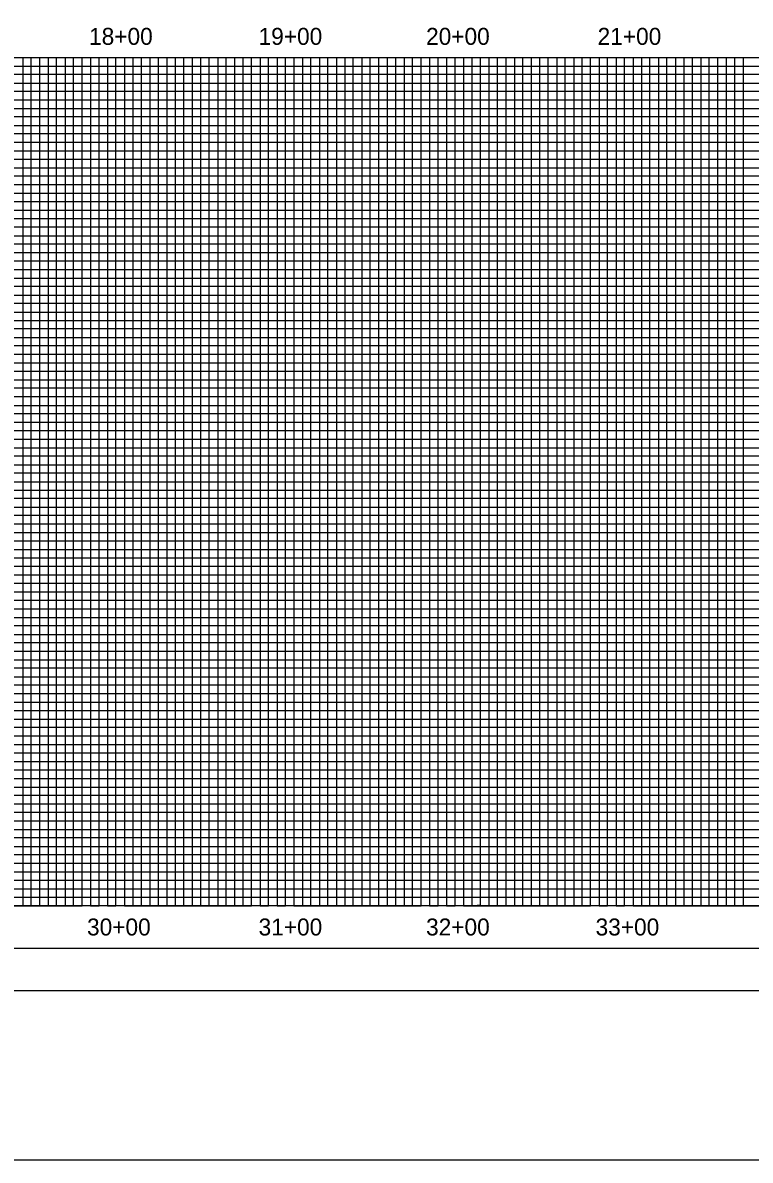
# Model space of a CAD drawing. Extents: x 505569 to 516904, y 436011 to 484484.
# Drawn here: x 506359 to 506788, y 483009 to 483679 of the extents above; entities that cross this region are included whole.
import ezdxf

# ---------------------------------------------------------------- set-up
doc = ezdxf.new("R2010")
doc.units = 0
for name, color, linetype in [('COGO Default Curve', 7, 'Continuous'), ('Exist Profile Cell', 7, 'Continuous'), ('Prop Grid Mask', 7, 'Continuous'), ('Prop Vertical Profile Curve Label', 7, 'Continuous'), ('Prop Vertical Profile Grade', 7, 'Continuous'), ('Prop Vertical Profile Grade Label', 7, 'Continuous'), ('Scratch_Level_2', 7, 'Continuous')]:
    doc.layers.add(name, color=color, linetype=linetype)

msp = doc.modelspace()

# ---------------------------------------------------------------- linework, layer by layer
at = {"layer": 'COGO Default Curve'}
for points in [[(506344.08, 483158.71), (506394.08, 483158.71), (506394.08, 483158.71), (506394.08, 483658.71), (506444.08, 483658.71), (506444.08, 483158.71), (506494.08, 483158.71), (506494.08, 483658.71), (506544.08, 483658.71), (506544.08, 483158.71), (506594.08, 483158.71), (506594.08, 483658.71), (506644.08, 483658.71), (506644.08, 483158.71), (506694.08, 483158.71), (506694.08, 483658.71), (506744.08, 483658.71), (506744.08, 483158.71), (506794.08, 483158.71)], [(505769.08, 483633.71), (507269.08, 483633.71)], [(507269.08, 483583.71), (505769.08, 483583.71), (505769.08, 483533.71), (507269.08, 483533.71)], [(507269.08, 483483.71), (505769.08, 483483.71), (505769.08, 483433.71), (507269.08, 483433.71)], [(507269.08, 483383.71), (505769.08, 483383.71), (505769.08, 483333.71), (507269.08, 483333.71)], [(507269.08, 483283.71), (505769.08, 483283.71), (505769.08, 483233.71), (507269.08, 483233.71)], [(507269.08, 483183.71), (505769.08, 483183.71)]]:
    msp.add_lwpolyline(points, dxfattribs=at)
at = {"layer": 'Prop Grid Mask'}
msp.add_lwpolyline([(505602.08, 483108.71), (507286.08, 483108.71), (507286.08, 484208.71), (505602.08, 484208.71)], close=True, dxfattribs=at)
at = {"layer": 'Prop Vertical Profile Curve Label'}
for p, q in [((505769.08, 483658.71), (507269.08, 483658.71)), ((507269.08, 483158.71), (505769.08, 483158.71)), ((505769.08, 483133.71), (507269.08, 483133.71))]:
    msp.add_line(p, q, dxfattribs=at)
msp.add_lwpolyline([(507269.08, 484183.71), (505769.08, 484183.71), (505769.08, 483133.71), (507269.08, 483133.71)], close=True, dxfattribs=at)
at = {"layer": 'Prop Vertical Profile Grade'}
for points in [[(505819.08, 483658.71), (507219.08, 483658.71), (507219.08, 483158.71), (505819.08, 483158.71)], [(505569.08, 483508.71), (506969.08, 483508.71), (506969.08, 483008.71), (505569.08, 483008.71)]]:
    msp.add_lwpolyline(points, close=True, dxfattribs=at)
at = {"layer": 'Prop Vertical Profile Grade Label'}
for p, q in [((505819.08, 483653.71), (507219.08, 483653.71)), ((507219.08, 483648.71), (505819.08, 483648.71)), ((505819.08, 483643.71), (507219.08, 483643.71)), ((507219.08, 483638.71), (505819.08, 483638.71)), ((505819.08, 483628.71), (507219.08, 483628.71)), ((507219.08, 483623.71), (505819.08, 483623.71)), ((505819.08, 483618.71), (507219.08, 483618.71)), ((507219.08, 483613.71), (505819.08, 483613.71)), ((505819.08, 483603.71), (507219.08, 483603.71)), ((507219.08, 483598.71), (505819.08, 483598.71)), ((505819.08, 483593.71), (507219.08, 483593.71)), ((507219.08, 483588.71), (505819.08, 483588.71)), ((505819.08, 483578.71), (507219.08, 483578.71)), ((507219.08, 483573.71), (505819.08, 483573.71)), ((505819.08, 483568.71), (507219.08, 483568.71)), ((507219.08, 483563.71), (505819.08, 483563.71)), ((505819.08, 483553.71), (507219.08, 483553.71)), ((507219.08, 483548.71), (505819.08, 483548.71)), ((505819.08, 483543.71), (507219.08, 483543.71)), ((507219.08, 483538.71), (505819.08, 483538.71)), ((505819.08, 483528.71), (507219.08, 483528.71)), ((507219.08, 483523.71), (505819.08, 483523.71)), ((505819.08, 483518.71), (507219.08, 483518.71)), ((507219.08, 483513.71), (505819.08, 483513.71)), ((505819.08, 483503.71), (507219.08, 483503.71)), ((507219.08, 483498.71), (505819.08, 483498.71)), ((505819.08, 483493.71), (507219.08, 483493.71)), ((507219.08, 483488.71), (505819.08, 483488.71)), ((505819.08, 483478.71), (507219.08, 483478.71)), ((507219.08, 483473.71), (505819.08, 483473.71)), ((505819.08, 483468.71), (507219.08, 483468.71)), ((507219.08, 483463.71), (505819.08, 483463.86)), ((505819.08, 483453.71), (507219.08, 483453.71)), ((507219.08, 483448.71), (505819.08, 483448.71)), ((505819.08, 483443.71), (507219.08, 483443.71)), ((507219.08, 483438.71), (505819.08, 483438.71)), ((505819.08, 483428.71), (507219.08, 483428.71)), ((507219.08, 483423.71), (505819.08, 483423.71)), ((505819.08, 483418.71), (507219.08, 483418.71)), ((507219.08, 483413.71), (505819.08, 483413.71)), ((505819.08, 483403.71), (507219.08, 483403.71)), ((507219.08, 483398.71), (505819.08, 483398.71)), ((505819.08, 483393.71), (507219.08, 483393.71)), ((507219.08, 483388.71), (505819.08, 483388.71)), ((505819.08, 483378.71), (507219.08, 483378.71)), ((507219.08, 483373.71), (505819.08, 483373.71)), ((505819.08, 483368.71), (507219.08, 483368.71)), ((507219.08, 483363.71), (505819.08, 483363.71)), ((505819.08, 483353.71), (507219.08, 483353.71)), ((507219.08, 483348.71), (505819.08, 483348.71)), ((505819.08, 483343.71), (507219.08, 483343.71)), ((507219.08, 483338.71), (505819.08, 483338.71)), ((505819.08, 483328.71), (507219.08, 483328.71)), ((507219.08, 483323.71), (505819.08, 483323.71)), ((505819.08, 483318.71), (507219.08, 483318.71)), ((507219.08, 483313.71), (505819.08, 483313.71)), ((505819.08, 483303.71), (507219.08, 483303.71)), ((507219.08, 483298.71), (505819.08, 483298.71)), ((505819.08, 483293.71), (507219.08, 483293.71)), ((507219.08, 483288.71), (505819.08, 483288.71)), ((505819.08, 483278.71), (507219.08, 483278.71)), ((507219.08, 483273.71), (505819.08, 483273.71)), ((505819.08, 483268.71), (507219.08, 483268.71)), ((507219.08, 483263.71), (505819.08, 483263.71)), ((505819.08, 483253.71), (507219.08, 483253.71)), ((507219.08, 483248.71), (505819.08, 483248.71)), ((505819.08, 483243.71), (507219.08, 483243.71)), ((507219.08, 483238.71), (505819.08, 483238.71)), ((505819.08, 483228.71), (507219.08, 483228.71)), ((507219.08, 483223.71), (505819.08, 483223.71)), ((505819.08, 483218.71), (507219.08, 483218.71)), ((507219.08, 483213.71), (505819.08, 483213.71)), ((505819.08, 483203.71), (507219.08, 483203.71)), ((507219.08, 483198.71), (505819.08, 483198.71)), ((505819.08, 483193.71), (507219.08, 483193.71)), ((507219.08, 483188.71), (505819.08, 483188.71)), ((505819.08, 483178.71), (507219.08, 483178.71)), ((507219.08, 483173.71), (505819.08, 483173.71)), ((505819.08, 483168.71), (507219.08, 483168.71)), ((505819.08, 483163.71), (507219.08, 483163.71))]:
    msp.add_line(p, q, dxfattribs=at)
for points in [[(506354.08, 483658.71), (506359.08, 483658.71), (506359.08, 483158.71), (506364.08, 483158.71), (506364.08, 483658.71), (506374.08, 483658.71), (506374.08, 483158.71), (506379.08, 483158.71), (506379.08, 483658.71), (506384.08, 483658.71), (506384.08, 483158.71), (506389.08, 483158.71), (506389.08, 483658.71), (506399.08, 483658.71), (506399.08, 483158.71), (506404.08, 483158.71), (506404.08, 483658.71), (506409.08, 483658.71), (506409.08, 483158.71), (506414.08, 483158.71), (506414.08, 483658.71), (506424.08, 483658.71), (506424.08, 483158.71), (506429.08, 483158.71), (506429.08, 483658.71), (506434.08, 483658.71), (506434.08, 483158.71), (506439.08, 483158.71), (506439.08, 483658.71), (506449.08, 483658.71), (506449.08, 483158.71), (506454.08, 483158.71), (506454.08, 483658.71), (506459.08, 483658.71), (506459.08, 483158.71), (506464.08, 483158.71), (506464.08, 483658.71), (506474.08, 483658.71), (506474.08, 483158.71), (506474.08, 483158.71), (506479.08, 483158.71), (506479.08, 483658.71), (506484.08, 483658.71), (506484.08, 483158.71), (506489.08, 483158.71), (506489.08, 483658.71), (506499.08, 483658.71), (506499.08, 483158.71), (506504.08, 483158.71), (506504.08, 483658.71), (506509.08, 483658.71), (506509.08, 483158.71), (506514.08, 483158.71), (506514.08, 483658.71), (506524.08, 483658.71), (506524.08, 483158.71), (506529.08, 483158.71), (506529.08, 483658.71), (506534.08, 483658.71), (506534.08, 483158.71), (506539.08, 483158.71), (506539.08, 483658.71), (506549.08, 483658.71), (506549.08, 483158.71), (506554.08, 483158.71), (506554.08, 483658.71), (506559.08, 483658.71), (506559.08, 483158.71), (506564.08, 483158.71), (506564.08, 483658.71), (506574.08, 483658.71), (506574.08, 483158.71), (506579.08, 483158.71), (506579.08, 483658.71), (506584.08, 483658.71), (506584.08, 483158.71), (506589.08, 483158.71), (506589.08, 483658.71), (506599.08, 483658.71), (506599.08, 483158.71), (506604.08, 483158.71), (506604.08, 483658.71), (506609.08, 483658.71), (506609.08, 483158.71), (506614.08, 483158.71), (506614.08, 483658.71), (506624.08, 483658.71), (506624.08, 483158.71), (506628.78, 483159.26), (506629.08, 483158.71), (506629.08, 483658.71), (506634.08, 483658.71), (506634.08, 483158.71), (506639.08, 483158.71), (506639.08, 483658.71), (506649.08, 483658.71), (506649.08, 483158.71), (506654.08, 483158.71)], [(506654.08, 483158.71), (506654.08, 483658.71), (506659.08, 483658.71), (506659.08, 483158.71), (506664.08, 483158.71), (506664.08, 483658.71), (506674.08, 483658.71), (506674.08, 483158.71), (506679.08, 483158.71), (506679.08, 483658.71), (506684.08, 483658.71), (506684.08, 483158.71), (506689.08, 483158.71), (506689.08, 483658.71), (506699.08, 483658.71), (506699.08, 483158.71), (506704.08, 483158.71), (506704.08, 483658.71), (506709.08, 483658.71), (506709.08, 483158.71), (506714.08, 483158.71), (506714.08, 483658.71), (506724.08, 483658.71), (506724.08, 483158.71), (506729.08, 483158.71), (506729.08, 483658.71), (506734.08, 483658.71), (506734.08, 483158.71), (506739.08, 483158.71), (506739.08, 483658.71), (506749.08, 483658.71), (506749.08, 483158.71), (506754.08, 483158.71), (506754.08, 483658.71), (506759.08, 483658.71), (506759.08, 483158.71), (506764.08, 483158.71), (506764.08, 483658.71), (506774.08, 483658.71), (506774.08, 483158.71), (506779.08, 483158.71), (506779.08, 483658.71), (506784.08, 483658.71), (506784.08, 483158.71), (506789.08, 483158.71)]]:
    msp.add_lwpolyline(points, dxfattribs=at)
at = {"layer": 'Scratch_Level_2'}
for p, q in [((506369.08, 483658.71), (506419.08, 483658.71)), ((506469.08, 483658.71), (506519.08, 483658.71)), ((506719.08, 483658.71), (506769.08, 483658.71))]:
    msp.add_line(p, q, dxfattribs=at)
for points in [[(506319.08, 483158.71), (506369.08, 483158.71), (506369.08, 483658.71), (506419.08, 483658.71), (506419.08, 483158.71), (506469.08, 483158.71), (506469.08, 483658.71), (506519.08, 483658.71), (506519.08, 483158.71), (506569.08, 483158.71), (506569.08, 483658.71), (506619.08, 483658.71), (506619.08, 483158.71), (506669.08, 483158.71), (506669.08, 483658.71), (506719.08, 483658.71), (506719.08, 483158.71), (506769.08, 483158.71), (506769.08, 483658.71), (506819.08, 483658.71)], [(506319.08, 483158.71), (506369.08, 483158.71), (506369.08, 483658.71), (506419.08, 483658.71), (506419.08, 483158.71), (506469.08, 483158.71), (506469.08, 483658.71), (506519.08, 483658.71), (506519.08, 483158.71), (506569.08, 483158.71), (506569.08, 483658.71), (506619.08, 483658.71), (506619.08, 483158.71), (506669.08, 483158.71), (506669.08, 483658.71), (506719.08, 483658.71), (506719.08, 483158.71), (506769.08, 483158.71), (506769.08, 483658.71), (506819.08, 483658.71)], [(507269.08, 483608.71), (505769.08, 483608.71)], [(507269.08, 483558.71), (505769.08, 483558.71), (505769.08, 483508.71), (507269.08, 483508.71)], [(507269.08, 483458.71), (505769.08, 483458.71), (505769.08, 483408.71), (507269.08, 483408.71)], [(507269.08, 483358.71), (505769.08, 483358.71), (505769.08, 483308.71), (507269.08, 483308.71)], [(507269.08, 483258.71), (505769.08, 483258.71), (505769.08, 483258.71), (505769.08, 483208.71), (507269.08, 483208.71)], [(507269.08, 483158.71), (505769.08, 483158.71)]]:
    msp.add_lwpolyline(points, dxfattribs=at)

# ---------------------------------------------------------------- texts
at = {"layer": 'Exist Profile Cell'}
for s, p in [('18+00', (506398.21, 483666.21)), ('19+00', (506498.21, 483666.21)), ('20+00', (506597.01, 483666.21)), ('21+00', (506698.21, 483666.21)), ('30+00', (506397.01, 483141.21)), ('31+00', (506498.21, 483141.21)), ('32+00', (506597.01, 483141.21)), ('33+00', (506697.01, 483141.21))]:
    msp.add_text(s, height=10, dxfattribs=at).set_placement(p)

doc.saveas('drawing.dxf')
